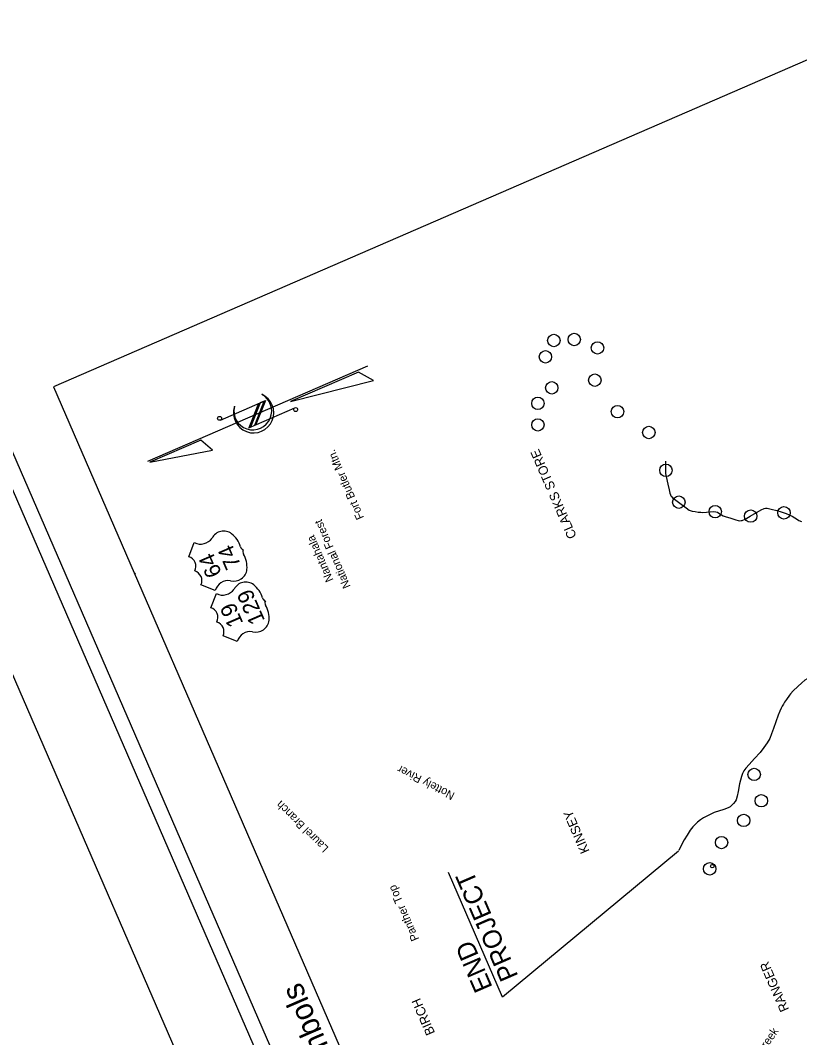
# Model space of a CAD drawing. Extents: x 442728 to 492797, y 479541 to 511293.
# Drawn here: x 471963 to 475924, y 487323 to 492495 of the extents above; entities that cross this region are included whole.
import ezdxf

# ---------------------------------------------------------------- set-up
doc = ezdxf.new("R2010")
doc.units = 0
for name, color, linetype in [('Default', 7, 'Continuous'), ('Old_Level_1', 7, 'Continuous'), ('Old_Level_22', 7, 'Continuous'), ('Prop DSN Text', 7, 'Continuous'), ('Prop Grid Mask', 7, 'Continuous'), ('Sheet North Arrow CELL', 7, 'Continuous'), ('Sheet Plot Border Outside CELL', 7, 'Continuous'), ('Sheet Title CELL', 7, 'Continuous')]:
    doc.layers.add(name, color=color, linetype=linetype)

msp = doc.modelspace()

# ---------------------------------------------------------------- linework, layer by layer
at = {"layer": 'Default'}
for p, q in [((475307.4, 488271.9), (474413.3, 487529.5)), ((474413.3, 487529.5), (474138.9, 488162.2))]:
    msp.add_line(p, q, dxfattribs=at)
for points in [[(475241.3, 490254.2), (475241.5, 490236), (475241.4, 490223), (475242.6, 490191.3), (475244.8, 490176.7), (475253.3, 490137.1), (475260.1, 490107.5), (475263.3, 490090.4), (475266.6, 490083.5), (475269.2, 490078.4), (475272.2, 490074.3), (475278.1, 490068.2), (475286.9, 490061), (475307.6, 490045.4), (475347.6, 490016), (475363, 490005.2), (475376.8, 489999.6), (475392.6, 489997.1), (475408, 489994.7), (475421.7, 489994.1), (475427.6, 489993.7), (475449.5, 489995), (475487, 489997.4), (475498.4, 489996.7), (475505.9, 489994.5), (475513.8, 489990.2), (475534.6, 489976.2), (475550.5, 489970.2), (475550.6, 489970.1), (475550.8, 489970.1), (475568.7, 489965), (475594.2, 489956.9), (475617.1, 489951.2), (475626, 489951.4), (475632.1, 489952.6), (475647.4, 489959.7), (475672.9, 489974.3), (475727.4, 490006), (475743.3, 490012.9), (475750.7, 490014.3), (475758, 490014.1), (475779.5, 490009.3), (475807.7, 490002.4), (475829.6, 489995.5), (475854.5, 489987), (475885, 489974.6), (475898.6, 489965.8), (475912.7, 489956.9), (475919.9, 489952.9), (475933.1, 489947.7)], [(472548.2, 489682.5), (472543.7, 489679.8)], [(476066.7, 489206.4), (476040, 489191.2), (476004.4, 489171.1), (475973.4, 489153.9), (475950.5, 489139.7), (475934.1, 489126.5), (475913.8, 489108.9), (475890.1, 489086), (475877.5, 489071.7), (475871.9, 489064.4), (475857.1, 489042.9), (475846.9, 489028.1), (475840.9, 489018.4), (475835.2, 489007.9), (475830.2, 488997.6), (475823.3, 488982.5), (475815, 488962.8), (475802.7, 488928.1)], [(475802.7, 488928.1), (475791.3, 488894.1), (475781.3, 488866.9), (475771.9, 488843.8), (475758.2, 488821.5), (475741.7, 488797.8), (475722.8, 488773), (475694.7, 488741.9), (475666.3, 488711), (475649.5, 488692.3), (475640.2, 488678.9), (475633.8, 488666.6), (475628, 488651.1)], [(475628, 488651.1), (475618.4, 488613.7), (475610.9, 488574.9), (475605.4, 488551.6), (475600.3, 488532.8), (475595.4, 488522.9), (475587.9, 488513.3), (475577.9, 488502.6), (475571, 488497.2), (475559.6, 488490.8), (475538.4, 488482.3), (475488.5, 488467), (475451.4, 488449.8), (475445.2, 488446.2), (475434.4, 488440.3), (475420.5, 488431.3), (475403.8, 488418.2), (475380.4, 488394.7), (475366.8, 488378.3), (475351.5, 488352.2), (475337.6, 488328.6), (475323.7, 488303.6), (475309.6, 488274.8)]]:
    msp.add_lwpolyline(points, dxfattribs=at)
for centre, radius in [((474674.5, 490867), 31.6), ((474778.2, 490872.2), 31.6), ((474896.3, 490829.5), 31.6), ((474631.7, 490784.2), 31.6), ((474882.7, 490665.7), 31.6), ((474663.9, 490626.4), 31.6), ((474593.3, 490547.7), 31.6), ((474997.9, 490505.5), 31.6), ((474593.3, 490438.2), 31.6), ((475157.4, 490399.3), 31.6), ((475244, 490207.3), 31.6), ((475309.6, 490045.6), 31.6), ((475494.7, 489997.2), 31.6), ((475844.1, 489991.4), 31.6), ((475674.9, 489974.5), 31.6), ((475692.8, 488661.3), 31.6), ((475728.7, 488527.6), 31.6), ((475639.4, 488427.4), 31.6), ((475526.9, 488315), 31.6), ((475466.5, 488181.6), 31.6), ((475479.5, 488195.2), 8.81)]:
    msp.add_circle(centre, radius, dxfattribs=at)
at = {"layer": 'Old_Level_1'}
msp.add_lwpolyline([(478660.8, 486844.6), (476245.2, 492415.3), (472131.1, 490631.3), (474546.6, 485060.7)], close=True, dxfattribs=at)
msp.add_lwpolyline([(478660.8, 486844.6), (476245.2, 492415.3), (472131.1, 490631.3), (474546.6, 485060.7)], close=True, dxfattribs=at)
msp.add_lwpolyline([(478660.8, 486844.6), (476245.2, 492415.3), (472131.1, 490631.3), (474546.6, 485060.7)], close=True, dxfattribs=at)
msp.add_lwpolyline([(478660.8, 486844.6), (476245.2, 492415.3), (472131.1, 490631.3), (474546.6, 485060.7)], close=True, dxfattribs=at)
at = {"layer": 'Prop Grid Mask'}
for p, q in [((472819.1, 489767.9), (472846.9, 489839.9)), ((472952.6, 489596.2), (472880.9, 489624.4)), ((473030.6, 489646.1), (473030.6, 489646.1)), ((472931.2, 489508.7), (472959, 489580.6)), ((473064.7, 489336.9), (472993, 489365.2)), ((473142.7, 489386.8), (473142.7, 489386.8))]:
    msp.add_line(p, q, dxfattribs=at)
for centre, radius, start, end in [((472879, 489902.9), 70.6, 243.0256, 325.3656), ((472996.3, 489831.2), 67.1, 52.9078, 151.9677), ((472950.2, 489777.1), 138.1, 17.6313, 51.1919), ((473101.1, 489822.3), 19.6, 189.9394, 254.6384), ((473112.9, 489793.6), 19.6, 150.0064, 217.0678), ((472803.7, 489719.1), 51.2, 332.648, 72.4987), ((472976.9, 489714), 138.1, 355.8194, 29.3915), ((473047.9, 489710.9), 67.1, 255.049, 354.1035), ((472834.6, 489646.4), 51.2, 334.589, 73.4331), ((473020.4, 489576.2), 70.6, 81.6457, 163.5445), ((472991.1, 489643.6), 70.6, 243.0256, 325.3656), ((473108.4, 489571.9), 67.1, 52.9078, 151.9677), ((473062.3, 489517.8), 138.1, 17.6313, 51.1919), ((473213.2, 489563), 19.6, 189.9394, 254.6384), ((473225, 489534.4), 19.6, 150.0064, 217.0678), ((472915.8, 489459.8), 51.2, 332.648, 72.4987), ((473089, 489454.8), 138.1, 355.8194, 29.3915), ((473160.1, 489451.6), 67.1, 255.049, 354.1035), ((472946.7, 489387.1), 51.2, 334.589, 73.4331), ((473132.5, 489316.9), 70.6, 81.6457, 163.5445)]:
    msp.add_arc(centre, radius, start, end, dxfattribs=at)
at = {"layer": 'Sheet North Arrow CELL'}
for p, q in [((473726.6, 490736.4), (472608.4, 490251.6)), ((472979.3, 490462.5), (473208.8, 490562)), ((473051.1, 490531.2), (473051.4, 490532.8)), ((473173, 490546.4), (473124.6, 490423.9)), ((473181.4, 490550.1), (473133, 490427.5)), ((473202.4, 490559.2), (473154, 490436.6)), ((473154, 490436.6), (473202.4, 490559.2)), ((473208.8, 490562), (473160.4, 490439.4)), ((473202.4, 490559.2), (473181.4, 490550.1)), ((473124.6, 490423.9), (473357.8, 490525)), ((473133, 490427.5), (473154, 490436.6))]:
    msp.add_line(p, q, dxfattribs=at)
for points in [[(473336.6, 490556.5), (473758, 490664), (473680.7, 490705.7)], [(472621.6, 490248.1), (472939.7, 490310.2), (472879.6, 490360)]]:
    msp.add_lwpolyline(points, close=True, dxfattribs=at)
for centre in [(473362.1, 490516.1), (472975.5, 490471.7)]:
    msp.add_circle(centre, 9.94, dxfattribs=at)
for centre, radius, start, end in [((473148.4, 490499.8), 102.4, 161.2825, 65.8365), ((473144.4, 490508.9), 96, 166.5375, 62.0711)]:
    msp.add_arc(centre, radius, start, end, dxfattribs=at)
at = {"layer": 'Sheet Plot Border Outside CELL'}
msp.add_lwpolyline([(465175.4, 504729.3), (475224.7, 481554), (490362.8, 488118.1), (480313.5, 511293.4)], close=True, dxfattribs=at)
at = {"layer": 'Sheet Title CELL'}
for points in [[(465680.5, 504507.1), (474512.4, 484138.8)], [(465779.3, 504467.9), (474253, 484926)]]:
    msp.add_lwpolyline(points, dxfattribs=at)

# ---------------------------------------------------------------- texts
at = {"layer": 'Default'}
for s, height, rotation, p in [('Fort Butler Mtn.', 41.378, 113.4424, (473710.7, 489967.1)), ('National Forest', 41.378, 113.4424, (473642.4, 489617.2)), ('Nantahala', 41.38, 113.4424, (473554.9, 489649.9)), ('Nottely River', 41.378, 152.8715, (474173.9, 488565.8)), ('Laurel Branch', 41.378, 135.3368, (473532.6, 488289.2)), ('PROJECT', 95, 113.4424, (474495.1, 487636.1)), ('Panther Top', 41.378, 113.4424, (473990.2, 487824.6)), ('END', 95, 113.4424, (474364.4, 487579.4)), ('Walker Mill Creek', 41.378, 55.135, (475570.8, 487000.1))]:
    msp.add_text(s, height=height, rotation=rotation, dxfattribs=at).set_placement(p)
at = {"layer": 'Old_Level_22'}
for s, height, p in [('CLARKS STORE', 47.289, (474791.6, 489871.4)), ('KINSEY', 47.29, (474856.7, 488271.4)), ('RANGER', 47.29, (475870.9, 487466.8)), ('BIRCH', 47.29, (474071.4, 487347.7))]:
    msp.add_text(s, height=height, rotation=113.4424, dxfattribs=at).set_placement(p)
at = {"layer": 'Prop DSN Text'}
for s, p in [('74', (473085.9, 489725.3)), ('64', (472988.2, 489682.9)), ('129', (473207.4, 489444.4)), ('19', (473097.1, 489431))]:
    msp.add_text(s, height=81.22, rotation=113.5056, dxfattribs=at).set_placement(p)
at = {"layer": 'Sheet Title CELL'}
msp.add_text('See Sheet 1B For Conventional Symbols', height=112.501, rotation=113.4424, dxfattribs=at).set_placement((474475.2, 485101.5))

doc.saveas('drawing.dxf')
